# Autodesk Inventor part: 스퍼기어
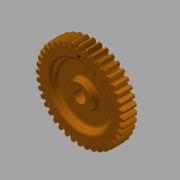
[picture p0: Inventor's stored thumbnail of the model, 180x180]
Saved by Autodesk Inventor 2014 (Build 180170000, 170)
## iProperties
Created: 2019-01
Part Number: 스퍼기어
Material: 알루미늄 6061
Document SubType Name: Modeling
Designer: mduedu
Density: 2.71 g/cm^3
Mass: 157.226 g
Surface Area: 186.47 cm^2
Volume: 58.017 cm^3
Appearance: 주황색
Author: mduedu
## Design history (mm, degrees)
sketch "스케치1"
  geometry: C1 r 37.5 at (0, 0); C2 r 40 at (0, 0); C3 r 42 at (0, 0); 1 further point
  constraints: 3 centre point, 3 coincident
  dimensions: "d0" = 75 diameter of C1; "d2" = 80 diameter of C2; "d3" = 84 diameter of C3
extrude "돌출1" new body sketch "스케치1" distance "d4" = 14; taper "d5" = 0 deg
sketch "스케치2"
  geometry: L1 (0, 0)-(-42, 0); L2 (0, 0)-(0, 42); L3 (-0.57, 0)-(-0.57, 41.996); L4 (-1.57, 0)-(-1.57, 39.969); L5 (-2.07, 0)-(-2.07, 37.443); A1 r 42 centre (0, 0) between (-42, 0) and (0, 42) reference; A2 r 9.223 centre (7.138, 36.933) between (-0.57, 41.996) and (-2.07, 37.443); A3 r 9.223 centre (-7.138, 36.933) between (2.07, 37.443) and (0.57, 41.996); A4 r 37.5 centre (0, 0) between (2.07, 37.443) and (-2.07, 37.443); A5 r 42 centre (0, 0) between (0.57, 41.996) and (-0.57, 41.996); 2 further points
  constraints: 12 point on circle, 10 end point, 4 centre point, 3 parallel, 3 symmetric about line, 2 coincident, 1 horizontal, 1 perpendicular, 5 other
  dimensions: "d6" = 0.5 distance between parallel lines of L4 L5; "d8" = 1 distance between parallel lines of L3 L4; "d9" = 1.57 distance between parallel lines of L2 L4
extrude "돌출2" join sketch "스케치2" stored distance "d10" = 14; taper "d11" = 0 deg
chamfer "모따기1" distance "d12" = 1; stored, may be unused: second distance "d13" = 2, angle "d14" = 45 deg
fillet "모깎기1" dims "d15" = 0.5
sketch "스케치3"
  geometry: C1 r 11 at (0, 0); 1 further point
  constraints: 1 centre point, 1 coincident
  dimensions: "d19" = 22 diameter of C1
extrude "돌출3" join sketch "스케치3" distance "d20" = 7; taper "d21" = 0 deg
fillet "모깎기2" dims "d22" = 3
sketch "스케치4"
  geometry: C1 r 11 at (0, 0); C2 r 27.5 at (0, 0); 1 further point
  constraints: 2 centre point, 2 coincident
  dimensions: "d23" = 22 diameter of C1; "d24" = 55 diameter of C2
extrude "돌출4" cut sketch "스케치4" distance "d25" = 6; taper "d26" = 0 deg
fillet "모깎기3" dims "d27" = 3
sketch "스케치5" dims "d28" = 66
  geometry: C1 r 1.5 at (0, 33); 2 further points
  constraints: 2 vertical alignment, 1 centre point, 1 coincident, 2 other
  dimensions: "d29" = 3 diameter of C1
extrude "돌출5" join sketch "스케치5" distance "d30" = 0.5; taper "d31" = 0 deg
sketch "스케치6"
  geometry: L1 (-2, 5.657)-(2, 5.657); L2 (2, 5.657)-(2, 7.8); L3 (2, 7.8)-(-2, 7.8); L4 (-2, 7.8)-(-2, 5.657); A1 r 6 centre (0, 0) between (-2, 5.657) and (2, 5.657); 1 further point
  constraints: 8 end point, 2 parallel, 2 point on circle, 1 centre point, 1 coincident, 1 horizontal, 1 perpendicular
  dimensions: "d32" = 13.8 dimension on A1 L3; "d34" = 4 distance of L2.end L3.end; "d35" = 12 diameter of A1
extrude "돌출6" cut sketch "스케치6" stored distance "d36" = 0.5; taper "d37" = 0 deg
chamfer "모따기2" distance "d38" = 1; stored, may be unused: second distance "d39" = 2, angle "d40" = 45 deg
node "솔리드1"
pattern_circular "원형 패턴1" dims "d17" = 360 deg
